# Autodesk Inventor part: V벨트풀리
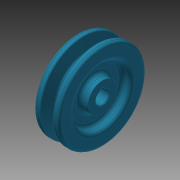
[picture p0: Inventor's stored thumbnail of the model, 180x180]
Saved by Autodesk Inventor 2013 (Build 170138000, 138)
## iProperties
Created: 2015-11
Part Number: V벨트풀리
Material: 강철, 탄소
Document SubType Name: Modeling
Designer: mduedu
Density: 1 g/cm^3
Author: mduedu
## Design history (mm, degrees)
sketch "스케치1"
  geometry: L1 (-9.5, 0)-(9.5, 0); L2 (0, 0)-(0, 32.7); L3 (-4.825, 32.7)-(-9.5, 32.7); L4 (-9.5, 32.7)-(-9.5, 0); L5 (0, 23.7)-(-2.074, 23.7); L6 (-2.074, 23.7)-(-4.825, 32.7); L7 (4.825, 32.7)-(9.5, 32.7); L8 (9.5, 32.7)-(9.5, 0); L9 (0, 23.7)-(2.074, 23.7); L10 (2.074, 23.7)-(4.825, 32.7); L11 (-9.5, 30)-(9.5, 30); 3 further points
  constraints: 22 end point, 7 point on line, 4 perpendicular, 3 symmetric about line, 1 coincident, 1 horizontal, 1 horizontal alignment, 1 midpoint, 1 vertical
  dimensions: "d0" = 19 distance of L1.start L1.end; "d2" = 65.4 diameter of L2.end L1 (derived); "d3" = 34 deg angle of L10 L6; "d4" = 6.3 distance between parallel lines of L11 L9; "d5" = 2.7 distance between parallel lines of L7 L11; "d6" = 8 distance of point (4, 30) point (-4, 30); "d7" = 60 diameter of L11 L1
revolve "회전1" sketch "스케치1" stored, may be unused: angle "d8" = 90 deg
sketch "스케치2"
  geometry: C1 r 21 at (0, 0); C2 r 11 at (0, 0); 1 further point
  constraints: 2 centre point, 2 coincident
  dimensions: "d9" = 42 diameter of C1; "d10" = 22 diameter of C2
extrude "돌출1" cut sketch "스케치2" distance "d11" = 6; taper "d12" = 0 deg
fillet "모깎기1" dims "d13" = 3
fillet "모깎기2" dims "d14" = 3
fillet "모깎기3" dims "d15" = 1, "d16" = 0.5, "d17" = 2
hole "구멍1" diameter "d20" = 10; stored, may be unused: countersink angle "d24" = 90 deg, drill point angle "d26" = 118 deg; dims "d18" = 10, "d19" = 10, "d21" = 6, "d22" = 4, "d23" = 2, "d25" = 8
sketch "스케치3"
  geometry: L1 (-1.5, 0)-(1.5, 0); L2 (1.5, 0)-(1.5, 6.4); L3 (1.5, 6.4)-(-1.5, 6.4); L4 (-1.5, 6.4)-(-1.5, 0); 2 further points
  constraints: 8 end point, 2 parallel, 1 coincident, 1 horizontal, 1 midpoint, 1 perpendicular
  dimensions: "d27" = 3 distance of L2.end L3.end; "d29" = 6.4 distance of L3.end L1.start
extrude "돌출2" cut sketch "스케치3" stored distance "d30" = 6; taper "d31" = 0 deg
chamfer "모따기1" distance "d32" = 0.5; stored, may be unused: second distance "d33" = 2, angle "d34" = 45 deg
node "솔리드1"
mirror "대칭1"
